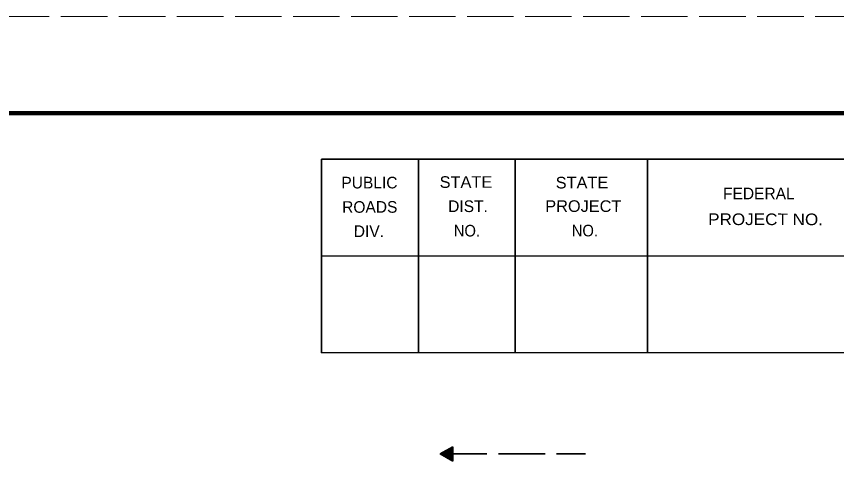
# Model space of a CAD drawing. Extents: x -58 to 622, y -372 to 68.
# Drawn here: x 465 to 549.8, y 21.9 to 68 of the extents above; entities that cross this region are included whole.
import ezdxf

# ---------------------------------------------------------------- set-up
doc = ezdxf.new("R2010")
doc.units = 0
doc.header["$LTSCALE"] = 0.8
doc.linetypes.add('LONG_DASHED', pattern=[7.5, 6, -1.5])
doc.layers.add('1', color=7, linetype='Continuous', lineweight=35)
doc.layers.add('61', color=7, linetype='Continuous', lineweight=35)

msp = doc.modelspace()

# ---------------------------------------------------------------- linework, layer by layer
at = {"layer": '1'}
for p, q in [((510.0782, 23.5257), (508.7701, 22.7703)), ((509.007, 22.6552), (509.007, 22.908)), ((509.0385, 22.6377), (509.0384, 22.9258)), ((509.0859, 22.6109), (509.086, 22.9527)), ((509.1313, 22.5855), (509.1312, 22.9785)), ((509.1602, 22.5693), (509.1602, 22.9948)), ((509.1863, 22.5546), (509.1863, 23.0096)), ((509.217, 22.5373), (509.2172, 23.027)), ((509.2454, 22.5214), (509.2455, 23.0432)), ((509.2792, 22.5024), (509.2792, 23.0622)), ((509.3098, 22.4852), (509.3098, 23.0796)), ((509.3374, 22.4697), (509.3374, 23.0953)), ((509.3787, 22.4465), (509.3787, 23.1186)), ((509.4001, 22.4346), (509.4002, 23.1308)), ((509.4384, 22.4131), (509.4384, 23.1523)), ((509.4737, 22.3933), (509.4734, 23.1723)), ((509.514, 22.3704), (509.514, 23.1952)), ((509.5522, 22.3491), (509.5523, 23.2169)), ((509.5797, 22.3337), (509.5796, 23.2324)), ((509.6067, 22.3185), (509.6067, 23.2478)), ((509.6334, 22.3036), (509.6334, 23.2628)), ((509.6502, 22.2942), (509.6502, 23.2724)), ((509.6725, 22.2816), (509.6724, 23.2852)), ((509.6959, 22.2684), (509.6961, 23.2982)), ((509.7237, 22.2528), (509.7237, 23.3141)), ((509.7543, 22.2355), (509.7544, 23.3313)), ((509.7788, 22.2218), (509.7788, 23.3452)), ((509.8032, 22.2081), (509.8032, 23.3591)), ((509.8117, 22.2035), (509.8117, 23.3638)), ((509.8484, 22.1827), (509.8486, 23.3848)), ((509.8714, 22.1698), (509.8714, 23.3977)), ((509.8852, 22.1621), (509.8853, 23.4055)), ((509.9074, 22.1497), (509.9074, 23.4181)), ((509.9426, 22.1299), (509.9426, 23.438)), ((509.9693, 22.1148), (509.9694, 23.4533)), ((510.0013, 22.0968), (510.0014, 23.4713)), ((510.0151, 22.0892), (510.0152, 23.4791)), ((510.0347, 22.0862), (510.0347, 23.4762)), ((510.0565, 22.0659), (510.0565, 23.5026)), ((510.0682, 22.0405), (510.0681, 23.5017)), ((510.0784, 22.015), (510.0782, 23.5257)), ((510.0784, 22.015), (508.7701, 22.7703)), ((508.8212, 22.7596), (508.8212, 22.8027)), ((508.8517, 22.7424), (508.8517, 22.8202)), ((508.8773, 22.7282), (508.8773, 22.8346)), ((508.8971, 22.7171), (508.897, 22.8457)), ((508.9193, 22.7046), (508.9193, 22.8584)), ((508.9331, 22.6967), (508.933, 22.8662)), ((508.9617, 22.6807), (508.9617, 22.8824))]:
    msp.add_line(p, q, dxfattribs=at)
at = {"layer": '1', "linetype": 'LONG_DASHED'}
msp.add_line((508.8232, 22.7838), (523.8232, 22.7838), dxfattribs=at)
at = {"layer": '61', "linetype": 'LONG_DASHED', "lineweight": 13}
msp.add_line((-58.4297, 67.9933), (621.5902, 67.9933), dxfattribs=at)
at = {"layer": '61'}
for p, q in [((506.5302, 53.2333), (506.5302, 33.2333)), ((516.5303, 53.2333), (516.5303, 33.2333)), ((530.2102, 53.2333), (530.2102, 33.2333)), ((604.5303, 43.2133), (496.5102, 43.2333))]:
    msp.add_line(p, q, dxfattribs=at)
at = {"layer": '61', "lineweight": 158}
msp.add_lwpolyline([(610.6102, 57.9933), (-28.4297, 57.9933), (-28.4297, -362.0267)], dxfattribs=at)
at = {"layer": '61'}
for points in [[(604.5102, 53.2533), (496.5302, 53.2333), (496.5302, 33.2333)], [(604.5102, 53.2533), (604.5102, 33.2533), (496.5302, 33.2333)]]:
    msp.add_lwpolyline(points, dxfattribs=at)

# ---------------------------------------------------------------- texts
for s, rotation, p in [('PUBLIC', 0.033, (498.5702, 50.2133)), ('FEDERAL', 0.007, (538.0303, 49.0933)), ('ROADS', 0.124, (498.6502, 47.6933)), ('DIST.', 0.056, (509.6103, 47.7733)), ('DIV.', 359.932, (499.8502, 45.1933))]:
    msp.add_text(s, height=1.201, rotation=rotation, dxfattribs=at).set_placement(p)
for s, rotation, width, p in [('STATE', 0.059, 1.05, (508.7302, 50.2733)), ('STATE', 0.059, 1.05, (520.7302, 50.2133)), ('PROJECT', 359.908, 1.05, (519.6503, 47.7933)), ('PROJECT NO.', 359.922, 1.1, (536.4902, 46.4333)), ('NO.', 359.852, 0.95, (510.1902, 45.2533)), ('NO.', 0.225, 0.95, (522.3903, 45.2533))]:
    msp.add_text(s, height=1.201, rotation=rotation, dxfattribs=dict(at, width=width)).set_placement(p)

doc.saveas('drawing.dxf')
